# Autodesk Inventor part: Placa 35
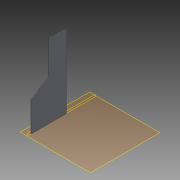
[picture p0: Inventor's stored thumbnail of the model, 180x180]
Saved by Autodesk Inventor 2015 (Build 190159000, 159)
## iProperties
Created: 2015-04
Part Number: Placa 35
Material: Generic
Document SubType Name: Modeling
Designer: suporte
Density: 1 g/cm^3
Appearance: Default
Author: suporte
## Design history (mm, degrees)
workplane "Work Plane1"
workplane "Work Plane2"
sketch "Sketch1"
  geometry: L1 (50, 25)-(-683, 25); L2 (50, 1025)-(-2050, 1025); L3 (50, 25)-(50, 1025); L4 (-683, 25)-(-1350, 1025); L5 (-2050, 25)-(-2050, 1775) reference; L6 (-1136.704, 525)-(-803.204, 25); L7 (-803.204, 25)-(-683, 25); L8 (-1136.704, 525)-(-2050, 525); L9 (-2050, 525)-(-2050, 1025); 1 further point
  constraints: 16 end point, 3 horizontal, 3 point on line, 1 collinear, 1 parallel, 1 perpendicular, 1 vertical, 1 other
  dimensions: "d0" = 733 distance of L1.start L1.end; "d1" = 1000 distance of L2.start L1.start; "d2" = 700 distance of L4.end L2.end; "d3" = 100 distance between parallel lines of L4 L6; "d4" = 500 distance of L5.start L8.end
extrude "Extrusion1" new body sketch "Sketch1" distance "d5" = 12.5; taper "d6" = 0 deg
body "Solid1"
node "Reference1"
